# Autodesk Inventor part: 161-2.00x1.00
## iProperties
Created: 2007-06
Part Number: 161-2.00x1.00
Document SubType Name: Modeling
Designer: btaylor
Density: 1 g/cm^3
Author: btaylor
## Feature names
1. Extrusion1
2. Extrusion2
3. Extrusion3
4. Extrusion4
5. Extrusion5
6. Fillet1
7. Fillet2
8. Fillet3
9. Fillet4
10. Extrusion6
11. Extrusion7
12. Extrusion8
13. Extrusion9
14. Extrusion10
15. Fillet5
16. Fillet6
17. Chamfer1
18. Chamfer2
19. Chamfer3
20. Fillet7
21. Fillet8
22. Fillet9
23. Fillet10
24. Fillet11
